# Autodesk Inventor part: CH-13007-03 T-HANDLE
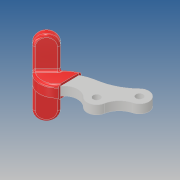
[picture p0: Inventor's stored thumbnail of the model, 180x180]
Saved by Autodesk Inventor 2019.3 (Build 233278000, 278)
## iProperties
Created: 2017-11
Part Number: CH-13007-03 T-HANDLE
Material: Ogólny
Document SubType Name: Modeling
Designer: Admin
Density: 1 g/cm^3
Appearance: Domyślna
Author: Admin
Revision Number: ÈÎºÎ
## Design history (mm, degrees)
feature "Ô²½Ç7"
node "Bryła1"
